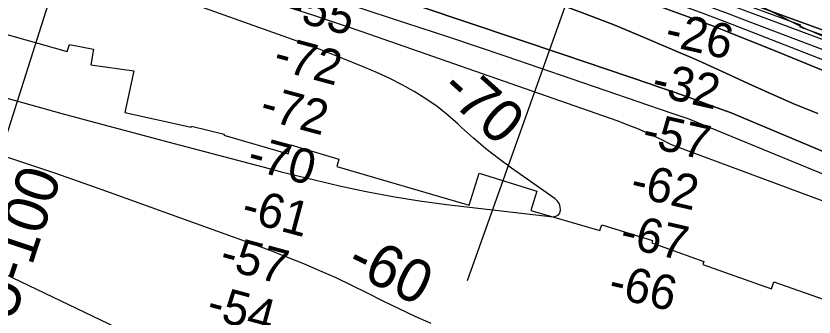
# Model space of a CAD drawing. Extents: x 3329297 to 3367176, y 649250 to 674653.
# Drawn here: x 3334604 to 3336153, y 670592 to 671176 of the extents above; entities that cross this region are included whole.
import ezdxf

# ---------------------------------------------------------------- set-up
doc = ezdxf.new("R2010")
doc.units = 0
for name, color, linetype in [('V-RIVR-EDGE', 7, 'Continuous'), ('V-RIVR-RANG', 7, 'Continuous'), ('V-RIVR-RANG-IDEN', 7, 'Continuous'), ('V-RRAP-RVMT', 7, 'Continuous'), ('V-TOPO-DPTH', 7, 'Continuous'), ('V-TOPO-MAJR', 7, 'Continuous'), ('V-TOPO-MINR', 7, 'Continuous'), ('V-TOPO-MINR-IDEN', 7, 'Continuous'), ('V-TOPO-WATR', 7, 'Continuous')]:
    doc.layers.add(name, color=color, linetype=linetype)

msp = doc.modelspace()

# ---------------------------------------------------------------- linework, layer by layer
at = {"layer": 'V-RIVR-EDGE'}
msp.add_spline([(3339166.4, 669632.4), (3339148.5, 669636.4), (3339138.8, 669636.8), (3339122.9, 669641.5), (3339105.1, 669646.9), (3339097, 669652), (3339093.1, 669656.3), (3339089.3, 669664.4), (3339086.6, 669669.1), (3339078.8, 669674.9), (3339053.6, 669688.2), (3339028.5, 669702.2), (3339020.7, 669706.5), (3339018, 669704.2), (3339012.6, 669704.6), (3339008.7, 669708.1), (3339008.3, 669710.4), (3339007.9, 669713.1), (3339007.6, 669715.1), (3338988.6, 669723.6), (3338974.6, 669732.6), (3338973.1, 669734.5), (3338972.7, 669738), (3338974.3, 669740.3), (3338974.3, 669743.8), (3338966.9, 669753.9), (3338965, 669758.6), (3338963.8, 669760.5), (3338956.5, 669764.4), (3338944.9, 669769.5), (3338928.2, 669778.1), (3338920.9, 669785.1), (3338906.6, 669803.3), (3338897.3, 669814.2), (3338888, 669824.7), (3338880.3, 669833.3), (3338874.1, 669838.7), (3338867.9, 669840.3), (3338862.1, 669843), (3338858.6, 669843), (3338858.6, 669845), (3338858.2, 669867.8), (3338860.6, 669870.9), (3338861.7, 669873.3), (3338861.8, 669876.4), (3338860.2, 669879.5), (3338854, 669882.6), (3338849, 669903.1), (3338843.6, 669917.5), (3338832.8, 669931.1), (3338822.7, 669940.8), (3338804.6, 669955.2), (3338800.7, 669956.8), (3338796, 669956.8), (3338788.7, 669955.3), (3338782.4, 669952.2), (3338775.5, 669955.7), (3338770.4, 669960.3), (3338765.4, 669965), (3338754.2, 669972.4), (3338742.6, 669981.4), (3338728.2, 669988.8), (3338714.7, 669995), (3338701.1, 670003.6), (3338693.4, 670012.1), (3338688, 670020.3), (3338682.6, 670033.5), (3338677.2, 670040.5), (3338665.2, 670046.3), (3338655.1, 670048.7), (3338655.5, 670045.9), (3338653.5, 670045.6), (3338643.5, 670046.4), (3338635.3, 670050.3), (3338633, 670053), (3338626.4, 670055.3), (3338615.2, 670057.3), (3338609, 670058.1), (3338601.6, 670062.8), (3338592.3, 670069.4), (3338582.2, 670071.7), (3338574.1, 670074.5), (3338568.3, 670078.7), (3338562.5, 670084.6), (3338561.3, 670087.7), (3338554.8, 670088.9), (3338551.3, 670089.3), (3338548.9, 670092), (3338544.3, 670098.6), (3338517.2, 670108.7), (3338513.3, 670111.8), (3338511.4, 670115.7), (3338497.8, 670118.9), (3338480, 670125.9), (3338471.5, 670130.2), (3338466.4, 670134.8), (3338451.7, 670140.3), (3338441.3, 670142.7), (3338438.2, 670142.3), (3338431.2, 670145.4), (3338420.3, 670150.1), (3338407.9, 670152.4), (3338393.2, 670156.7), (3338378.5, 670165.7), (3338345.2, 670189.4), (3338316.5, 670206.6), (3338280.9, 670231.5), (3338237.6, 670254.5), (3338210.4, 670270.8), (3338182.6, 670289.9), (3338148.9, 670317.5), (3338126.1, 670336.9), (3338116, 670348.2), (3338106.7, 670356.8), (3338093.6, 670363.8), (3338076.9, 670368.9), (3338057.5, 670376.3), (3338042.8, 670383.3), (3338026.5, 670392.6), (3338007.2, 670402.4), (3337994, 670405.5), (3337971.5, 670413.3), (3337948.7, 670420.8), (3337916.5, 670434), (3337912.6, 670440.6), (3337911.1, 670448.8), (3337908.8, 670453.8), (3337904.5, 670455.8), (3337891, 670459.7), (3337883.6, 670464.7), (3337879.4, 670466.7), (3337872.4, 670467.1), (3337862.7, 670467.1), (3337849.9, 670466), (3337839.8, 670463.7), (3337826.2, 670462.6), (3337810.7, 670465.7), (3337802.2, 670469.2), (3337788.3, 670478.2), (3337779.7, 670480.5), (3337774.3, 670481.7), (3337768.9, 670486.7), (3337764.6, 670490.6), (3337755.7, 670494.9), (3337749.1, 670496.9), (3337745.3, 670497.3), (3337740.6, 670495.3), (3337738.7, 670496.1), (3337735.2, 670499.2), (3337729.8, 670503.5), (3337724.7, 670508.2), (3337720.1, 670512.1), (3337706.1, 670514.4), (3337677.9, 670531.2), (3337643.8, 670545.2), (3337600.8, 670567), (3337560.1, 670585.4), (3337510.1, 670611.9), (3337463.3, 670636.4), (3337442.4, 670644.2), (3337416.8, 670652.4), (3337405.5, 670657.5), (3337401.7, 670661.4), (3337400.1, 670663.3), (3337395.5, 670665.7), (3337388.9, 670666.1), (3337376.9, 670670.8), (3337362.9, 670677.8), (3337340.9, 670690.6), (3337309.5, 670707), (3337291.3, 670714.8), (3337276.2, 670723), (3337252.6, 670737), (3337220, 670756.8), (3337155, 670798.5), (3337124.4, 670821.1), (3337111.2, 670827.3), (3337094.2, 670832.8), (3337076, 670836.7), (3337050.4, 670842.6), (3337028.7, 670849.6), (3337007.8, 670860.5), (3336991.9, 670867.9), (3336983.4, 670871.1), (3336969, 670873.4), (3336939.9, 670875.4), (3336902, 670884.4), (3336863.6, 670895.8), (3336821.4, 670910.6), (3336786.5, 670926.2), (3336740, 670949.6), (3336682.3, 670976.1), (3336635.4, 670997.2), (3336603.7, 671013.5), (3336585.5, 671022.5), (3336583.2, 671026.4), (3336580.1, 671031.1), (3336576.2, 671034.6), (3336549.5, 671045.1), (3336500.2, 671058), (3336451.4, 671070.2), (3336425.4, 671074.5), (3336399.8, 671076.5), (3336361.1, 671078.9), (3336337.4, 671082.8), (3336313.4, 671088.3), (3336290.9, 671094.6), (3336280.5, 671097.3), (3336275.4, 671097.3), (3336257.6, 671097.4), (3336194.8, 671123.9), (3336129.4, 671154.3), (3336078.6, 671179.7), (3336032.9, 671203), (3335979.5, 671230.3), (3335943, 671245.5), (3335907.8, 671259.2), (3335894.2, 671264.7), (3335887.6, 671265.5), (3335873.3, 671273.6), (3335871.4, 671277.1), (3335862.9, 671281.4), (3335831.1, 671293.5), (3335799.3, 671308.7), (3335763.7, 671327.4), (3335724.6, 671346.9), (3335714.5, 671352), (3335703.3, 671355.1), (3335699, 671358.2), (3335680, 671369.9), (3335645.9, 671385.5), (3335603.7, 671399.2), (3335573.1, 671406.6), (3335518.1, 671419.9), (3335470.4, 671436.7), (3335434, 671449.6), (3335405.3, 671466), (3335398, 671471), (3335385.9, 671471.1), (3335366.9, 671468.8), (3335346, 671463), (3335338.6, 671464.6), (3335338.6, 671467.3), (3335339, 671475.8), (3335337.9, 671478.9), (3335334.4, 671482), (3335319.7, 671486.7), (3335303, 671491), (3335280.1, 671488.4), (3335259.2, 671479.5), (3335245.6, 671472.2), (3335233.1, 671471.4), (3335223.8, 671474.2), (3335210.7, 671482), (3335198.7, 671485.9), (3335156.4, 671487.5), (3335124.6, 671488.4), (3335114.1, 671484.9), (3335094.7, 671474.1), (3335085.4, 671473.4), (3335075.3, 671475.7), (3335065.6, 671477.7), (3335064.9, 671478.5), (3335067.6, 671483.1), (3335066.8, 671484.7), (3335063.7, 671489.3), (3335039.7, 671501.4), (3335020.7, 671509.2), (3335003.3, 671512), (3334994.8, 671515.5), (3334990.9, 671517), (3334963, 671533.4), (3334933.2, 671549.4), (3334916.1, 671551.3), (3334894.4, 671557.6), (3334863.4, 671571.2), (3334847.9, 671581.8), (3334834.8, 671588), (3334809.2, 671598.5), (3334767.8, 671617.2), (3334744.9, 671627.8), (3334711.2, 671642.2), (3334691.4, 671649.2), (3334670.1, 671653.2), (3334647.6, 671659.8), (3334620.1, 671672.3), (3334605.4, 671678.5), (3334581, 671683.2), (3334555.8, 671689.1), (3334542.2, 671688.4), (3334534.1, 671688.8), (3334531.4, 671696.6), (3334523.7, 671706.3), (3334505.8, 671714.8), (3334480.3, 671719.2), (3334460.5, 671721.9), (3334457, 671720.4), (3334455, 671716.9), (3334456.6, 671713.8), (3334463.2, 671714.6), (3334467.4, 671712.2), (3334467.4, 671710.3), (3334462.8, 671708.4), (3334446.9, 671706.8), (3334429, 671707.7), (3334403.5, 671713.9), (3334397.7, 671718.6), (3334391.5, 671722.9), (3334378.7, 671723.7), (3334340.3, 671727.3), (3334305.4, 671730.1), (3334290.3, 671730.1), (3334281.3, 671731.7), (3334271.7, 671734.8), (3334266.2, 671735.6), (3334258.1, 671732.9), (3334246.4, 671726.7), (3334241.4, 671726.4), (3334232.5, 671729.5), (3334218.9, 671729.9), (3334190.6, 671730.7), (3334179, 671731.9), (3334163.5, 671737.4), (3334156.1, 671736.6), (3334151.4, 671732.4), (3334148.3, 671732.4), (3334142.5, 671735.9), (3334132.8, 671736.3), (3334110.7, 671737.5), (3334106.9, 671739.5), (3334099.9, 671744.2), (3334081.3, 671748.1), (3334072.8, 671747.7), (3334041.7, 671753.6), (3334018.1, 671757.5), (3334010.3, 671760.3), (3333999.9, 671767.7), (3333992.1, 671772), (3333987.1, 671771.2), (3333984.4, 671768.5), (3333980.1, 671768.5), (3333976.6, 671772.8), (3333969.7, 671775.1), (3333958.8, 671778.2), (3333949.9, 671783.3), (3333945.6, 671782.9), (3333941.4, 671782.2), (3333931.3, 671788), (3333925.9, 671788), (3333915.4, 671788.8), (3333900.3, 671791.6), (3333878.2, 671798.6), (3333856.9, 671811.1), (3333845.7, 671822.7), (3333832.9, 671829), (3333818.2, 671834.8), (3333817.4, 671837.2), (3333813.5, 671837.5), (3333800.4, 671841.8), (3333795.7, 671845), (3333793.8, 671851.6), (3333792.2, 671854.3), (3333782.9, 671858.2), (3333767.9, 671869.5), (3333755.5, 671879.6), (3333746.2, 671884.6), (3333742.7, 671886.2), (3333733.8, 671885.8), (3333721, 671886.6), (3333714.4, 671889.8), (3333707.8, 671895.2), (3333701.6, 671902.6), (3333697, 671908.4), (3333690.4, 671913.1), (3333677.2, 671920.5), (3333664.5, 671934.9), (3333650.9, 671945.8), (3333635, 671952), (3333625.8, 671959.8), (3333617.6, 671968.7), (3333606.4, 671969.9), (3333601, 671974.2), (3333597.9, 671978.1), (3333590.1, 671989), (3333572.4, 672009.2), (3333553.4, 672029.4), (3333532.1, 672045.7), (3333511.2, 672062.1), (3333486.4, 672080.3), (3333466.3, 672090.9), (3333451.6, 672102.9), (3333445.8, 672109.5), (3333446.6, 672115), (3333429.2, 672126.2), (3333421.4, 672137.9), (3333420.7, 672148.8), (3333415.3, 672151.1), (3333404.7, 672151.6)], degree=3, dxfattribs=at)
at = {"layer": 'V-RIVR-RANG'}
for p, q in [((3335003.7, 672263), (3334580, 670928.6)), ((3335950.1, 671980.4), (3335479.2, 670662))]:
    msp.add_line(p, q, dxfattribs=at)
at = {"layer": 'V-RRAP-RVMT'}
for p, q in [((3336127, 671158.3), (3336006.7, 671202)), ((3336125.6, 671154.2), (3336127, 671158.3)), ((3334566.8, 671145.2), (3334703.4, 671106.7)), ((3336227.2, 671118), (3336125.6, 671154.2)), ((3334703.4, 671106.7), (3334707.9, 671120.8)), ((3334707.9, 671120.8), (3334754.4, 671111.2)), ((3334754.4, 671111.2), (3334749, 671081.2)), ((3334749, 671081.2), (3334832.5, 671069.4)), ((3334832.5, 671069.4), (3334814.9, 670988.7)), ((3334814.9, 670988.7), (3334944, 670960.2)), ((3334944, 670960.2), (3334944.5, 670962.2)), ((3334944.5, 670962.2), (3335007.6, 670946.7)), ((3335007.6, 670946.7), (3335007.1, 670944.4)), ((3335007.1, 670944.4), (3335131.8, 670908.6)), ((3335131.8, 670908.6), (3335137.1, 670925.7)), ((3335137.1, 670925.7), (3335230.3, 670898.2)), ((3335230.3, 670898.2), (3335226.6, 670884)), ((3335226.6, 670884), (3335483.5, 670808.9)), ((3335483.5, 670808.9), (3335502.6, 670870.7)), ((3335502.6, 670870.7), (3335614.9, 670836.4)), ((3335614.9, 670836.4), (3335602.7, 670798.5)), ((3335602.7, 670798.5), (3335736.8, 670760.1)), ((3335736.8, 670760.1), (3335740.6, 670771.1)), ((3335740.6, 670771.1), (3335839, 670740.3)), ((3335839, 670740.3), (3335837.7, 670735.8)), ((3335837.7, 670735.8), (3335938.8, 670699.4)), ((3335938.8, 670699.4), (3335936.7, 670693.7)), ((3335936.7, 670693.7), (3336069.9, 670646.6)), ((3336069.9, 670646.6), (3336074.6, 670660.3)), ((3336074.6, 670660.3), (3336183.3, 670622.4))]:
    msp.add_line(p, q, dxfattribs=at)
at = {"layer": 'V-TOPO-DPTH'}
for points in [[(3334414.8, 671708.4), (3335247.6, 671481.7), (3335255, 671479.7), (3335262.3, 671477.6), (3335269.6, 671475.4), (3335276.9, 671473.1), (3335284.2, 671470.8), (3335291.5, 671468.4), (3335298.7, 671465.9), (3335305.9, 671463.3), (3335880.5, 671254.6), (3335895, 671249.3), (3335909.5, 671244), (3335924, 671238.7), (3335938.5, 671233.3), (3335958.7, 671225.9), (3335963.1, 671224.3), (3335967.5, 671222.6), (3335972, 671221), (3335976.4, 671219.4), (3336088.2, 671178.3), (3336148.6, 671156.1), (3336208.9, 671133.8)], [(3336208.9, 671133.8), (3336148.6, 671156.1), (3336088.2, 671178.3), (3335976.4, 671219.4), (3335972, 671221), (3335967.5, 671222.6), (3335963.1, 671224.3), (3335958.7, 671225.9), (3335938.5, 671233.3), (3335924, 671238.7), (3335909.5, 671244), (3335895, 671249.3), (3335880.5, 671254.6), (3335305.9, 671463.3), (3335298.7, 671465.9), (3335291.5, 671468.4), (3335284.2, 671470.8), (3335276.9, 671473.1), (3335269.6, 671475.4), (3335262.3, 671477.6), (3335255, 671479.7), (3335247.6, 671481.7), (3334414.8, 671708.4)], [(3336568.3, 670959.4), (3336013.3, 671169.7), (3335986.6, 671179.7), (3335959.9, 671189.7), (3335933.2, 671199.6), (3335906.5, 671209.5), (3335826.2, 671239), (3335759.3, 671263.3), (3335692.1, 671287.1), (3335624.8, 671310.4), (3335557.4, 671333.3), (3335330, 671409.2), (3335304.9, 671417.4), (3335279.7, 671425.4), (3335254.4, 671433), (3335229, 671440.4), (3334753, 671576.1), (3334687.6, 671594.6), (3334622.2, 671613.1), (3334556.7, 671631.3)], [(3336568.3, 670959.4), (3336013.3, 671169.7), (3335986.6, 671179.7), (3335959.9, 671189.7), (3335933.2, 671199.6), (3335906.5, 671209.5), (3335826.2, 671239), (3335759.3, 671263.3), (3335692.1, 671287.1), (3335624.8, 671310.4), (3335557.4, 671333.3), (3335330, 671409.2), (3335304.9, 671417.4), (3335279.7, 671425.4), (3335254.4, 671433), (3335229, 671440.4), (3334753, 671576.1), (3334687.6, 671594.6), (3334622.2, 671613.1), (3334556.7, 671631.3)], [(3334388.2, 671617), (3334613, 671565.5), (3334723.3, 671539.6), (3334833.5, 671513), (3334943.4, 671485.3), (3335053.2, 671456.8), (3335248.6, 671404.9), (3335260.4, 671401.7), (3335272.3, 671398.3), (3335284, 671394.7), (3335295.7, 671391), (3335373.3, 671365.6), (3335423.7, 671348.8), (3335473.9, 671331.7), (3335524, 671314.1), (3335574, 671296.1), (3335929.9, 671166.1), (3335941.2, 671161.9), (3335952.5, 671157.7), (3335963.8, 671153.3), (3335975, 671148.9), (3336067.1, 671112.2), (3336124.2, 671089), (3336181.1, 671065.3)], [(3336181.1, 671065.3), (3336124.2, 671089), (3336067.1, 671112.2), (3335975, 671148.9), (3335963.8, 671153.3), (3335952.5, 671157.7), (3335941.2, 671161.9), (3335929.9, 671166.1), (3335574, 671296.1), (3335524, 671314.1), (3335473.9, 671331.7), (3335423.7, 671348.8), (3335373.3, 671365.6), (3335295.7, 671391), (3335284, 671394.7), (3335272.3, 671398.3), (3335260.4, 671401.7), (3335248.6, 671404.9), (3335053.2, 671456.8), (3334943.4, 671485.3), (3334833.5, 671513), (3334723.3, 671539.6), (3334613, 671565.5), (3334388.2, 671617)], [(3334519.3, 671499.2), (3334616.5, 671474.7), (3334713.8, 671450.9), (3334811.4, 671428.4), (3334909.3, 671406.5), (3335200.3, 671343.3), (3335227.2, 671337.1), (3335253.9, 671330.3), (3335280.3, 671322.7), (3335306.7, 671314.5), (3335592.6, 671221), (3335650.8, 671201.1), (3335708.7, 671180.2), (3335765.9, 671157.8), (3335822.8, 671134.3), (3335889.7, 671105.7), (3335912.8, 671095.7), (3335935.8, 671085.6), (3335958.7, 671075.2), (3335981.6, 671064.8), (3336024.9, 671044.8), (3336069.5, 671024.7), (3336114.4, 671005.1), (3336159.7, 670986.5)], [(3334519.3, 671499.2), (3334616.5, 671474.7), (3334713.8, 671450.9), (3334811.4, 671428.4), (3334909.3, 671406.5), (3335200.3, 671343.3), (3335227.2, 671337.1), (3335253.9, 671330.3), (3335280.3, 671322.7), (3335306.7, 671314.5), (3335592.6, 671221), (3335650.8, 671201.1), (3335708.7, 671180.2), (3335765.9, 671157.8), (3335822.8, 671134.3), (3335889.7, 671105.7), (3335912.8, 671095.7), (3335935.8, 671085.6), (3335958.7, 671075.2), (3335981.6, 671064.8), (3336024.9, 671044.8), (3336069.5, 671024.7), (3336114.4, 671005.1), (3336159.7, 670986.5)], [(3336780.8, 670656.1), (3335991.8, 670987.8), (3335955.6, 671001.1), (3335919.3, 671014.3), (3335882.8, 671027.2), (3335846.3, 671039.8), (3335835.6, 671043.5), (3335793.7, 671057.8), (3335751.7, 671072.1), (3335709.8, 671086.3), (3335667.8, 671100.5), (3335296, 671225.8), (3335263.7, 671236.5), (3335231.4, 671247), (3335199, 671257.2), (3335166.5, 671267.3), (3335055.9, 671301), (3334968, 671327.5), (3334879.9, 671353.6), (3334791.7, 671379.1), (3334703.4, 671404.2), (3334375.4, 671496.3)], [(3334375.4, 671496.3), (3334703.4, 671404.2), (3334791.7, 671379.1), (3334879.9, 671353.6), (3334968, 671327.5), (3335055.9, 671301), (3335166.5, 671267.3), (3335199, 671257.2), (3335231.4, 671247), (3335263.7, 671236.5), (3335296, 671225.8), (3335667.8, 671100.5), (3335709.8, 671086.3), (3335751.7, 671072.1), (3335793.7, 671057.8), (3335835.6, 671043.5), (3335846.3, 671039.8), (3335882.8, 671027.2), (3335919.3, 671014.3), (3335955.6, 671001.1), (3335991.8, 670987.8), (3336780.8, 670656.1)]]:
    msp.add_lwpolyline(points, dxfattribs=at)
at = {"layer": 'V-TOPO-MAJR'}
for points in [[(3336703.6, 670649.6), (3335910.2, 670975.4), (3335892.7, 670981.5), (3335875.2, 670987.6), (3335554.9, 671097), (3335499.4, 671115.8), (3335443.7, 671134.5), (3335388, 671152.9), (3335332.3, 671171.1), (3335245.6, 671199.1), (3335233.1, 671203.1), (3335220.6, 671207.1), (3335208, 671210.9), (3335195.4, 671214.7), (3334355.2, 671464.4)], [(3334192.5, 670861.7), (3335001.2, 670474.8)]]:
    msp.add_lwpolyline(points, dxfattribs=at)
at = {"layer": 'V-TOPO-MINR'}
for points in [[(3336645.9, 670952.8), (3336032.9, 671180.5), (3335998.3, 671193.3), (3335963.7, 671206.1), (3335929.1, 671218.9), (3335894.6, 671231.7), (3335882.5, 671236.1), (3335841.8, 671251), (3335801, 671265.6), (3335760.2, 671280), (3335719.3, 671294.3), (3335352.7, 671420.8), (3335318.7, 671432.2), (3335284.6, 671443.4), (3335250.4, 671454.2), (3335216, 671464.6), (3335115.5, 671494.5), (3335030.7, 671519.3), (3334945.8, 671543.8), (3334860.8, 671567.8), (3334775.7, 671591.3), (3334427.5, 671686.5)], [(3336568.3, 670959.4), (3336013.3, 671169.7), (3335986.6, 671179.7), (3335959.9, 671189.7), (3335933.2, 671199.6), (3335906.5, 671209.5), (3335826.2, 671239), (3335759.3, 671263.3), (3335692.1, 671287.1), (3335624.8, 671310.4), (3335557.4, 671333.3), (3335330, 671409.2), (3335304.9, 671417.4), (3335279.7, 671425.4), (3335254.4, 671433), (3335229, 671440.4), (3334753, 671576.1), (3334687.6, 671594.6), (3334622.2, 671613.1), (3334556.7, 671631.3)], [(3336181.1, 671065.3), (3336124.2, 671089), (3336067.1, 671112.2), (3335975, 671148.9), (3335963.8, 671153.3), (3335952.5, 671157.7), (3335941.2, 671161.9), (3335929.9, 671166.1), (3335574, 671296.1), (3335524, 671314.1), (3335473.9, 671331.7), (3335423.7, 671348.8), (3335373.3, 671365.6), (3335295.7, 671391), (3335284, 671394.7), (3335272.3, 671398.3), (3335260.4, 671401.7), (3335248.6, 671404.9), (3335053.2, 671456.8), (3334943.4, 671485.3), (3334833.5, 671513), (3334723.3, 671539.6), (3334613, 671565.5), (3334388.2, 671617)], [(3336275.8, 671049.7), (3335993.9, 671159.1), (3335975.1, 671166.4), (3335956.2, 671173.6), (3335937.2, 671180.6), (3335918.3, 671187.6), (3335735.6, 671254.6), (3335659.4, 671282.1), (3335583.1, 671309), (3335506.4, 671335.1), (3335429.6, 671360.7), (3335311.4, 671399.5), (3335293.6, 671405.2), (3335275.6, 671410.7), (3335257.6, 671416), (3335239.6, 671421.1), (3334519.3, 671619.5)], [(3336159.7, 670986.5), (3336114.4, 671005.1), (3336069.5, 671024.7), (3336024.9, 671044.8), (3335981.6, 671064.8), (3335958.7, 671075.2), (3335935.8, 671085.6), (3335912.8, 671095.7), (3335889.7, 671105.7), (3335822.8, 671134.3), (3335765.9, 671157.8), (3335708.7, 671180.2), (3335650.8, 671201.1), (3335592.6, 671221), (3335306.7, 671314.5), (3335280.3, 671322.7), (3335253.9, 671330.3), (3335227.2, 671337.1), (3335200.3, 671343.3), (3334909.3, 671406.5), (3334811.4, 671428.4), (3334713.8, 671450.9), (3334616.5, 671474.7), (3334519.3, 671499.2)], [(3336780.8, 670656.1), (3335991.8, 670987.8), (3335955.6, 671001.1), (3335919.3, 671014.3), (3335882.8, 671027.2), (3335846.3, 671039.8), (3335835.6, 671043.5), (3335793.7, 671057.8), (3335751.7, 671072.1), (3335709.8, 671086.3), (3335667.8, 671100.5), (3335296, 671225.8), (3335263.7, 671236.5), (3335231.4, 671247), (3335199, 671257.2), (3335166.5, 671267.3), (3335055.9, 671301), (3334968, 671327.5), (3334879.9, 671353.6), (3334791.7, 671379.1), (3334703.4, 671404.2), (3334375.4, 671496.3)], [(3334358.3, 671422.8), (3335013.2, 671229.8), (3335046.1, 671219.9), (3335079, 671209.9), (3335111.8, 671199.7), (3335144.6, 671189.3), (3335177.3, 671178.6), (3335209.9, 671167.8), (3335242.4, 671156.8), (3335274.9, 671145.6), (3335769.8, 670972.8), (3335791.5, 670964.8), (3335813, 670956.2), (3335834.1, 670946.8), (3335855, 670936.9), (3335875, 670926.9), (3336707.5, 670617.4)], [(3334584, 671017.1), (3334692.8, 670987), (3334801.8, 670957.5), (3334910.9, 670928.4), (3335107.8, 670876.5), (3335118.6, 670873.7), (3335129.4, 670871), (3335140.2, 670868.3), (3335151, 670865.7), (3335231.9, 670846.6), (3335283.4, 670835.5), (3335335.1, 670825.5), (3335387, 670817.3), (3335439.2, 670810.4), (3335646, 670786.6), (3335651.6, 670787.4), (3335656.1, 670789.6), (3335659, 670793.7), (3335660.8, 670799.1), (3335660.1, 670805.6), (3335658.3, 670811.6), (3335654.7, 670816.8), (3335649.9, 670821.4), (3335565.7, 670880.6), (3335540.4, 670899.2), (3335515.8, 670918.4), (3335492, 670938.7), (3335468.7, 670959.6), (3335462, 670965.9), (3335442, 670983.5), (3335421.2, 671000.1), (3335399.3, 671015.2), (3335376.7, 671029.4), (3335353.3, 671042.3), (3335329.5, 671054.5), (3335305.2, 671065.6), (3335280.7, 671076.1), (3335218.8, 671100.9), (3335206.6, 671105.7), (3335194.3, 671110.5), (3335182, 671115.1), (3335169.7, 671119.6), (3334875, 671225.2)], [(3334583.4, 670903.6), (3334680.8, 670870.9), (3334777.8, 670837), (3335064.8, 670733.5), (3335077.1, 670729), (3335089.4, 670724.4), (3335101.5, 670719.7), (3335113.7, 670714.8), (3335161.6, 670695.6), (3335193.1, 670682.4), (3335224.3, 670668.7), (3335255.1, 670654), (3335285.6, 670638.7), (3335316.1, 670623.3), (3335346.8, 670608.3), (3335377.8, 670593.9), (3335409, 670580)]]:
    msp.add_lwpolyline(points, dxfattribs=at)
at = {"layer": 'V-TOPO-WATR'}
msp.add_lwpolyline([(3336208.9, 671133.8), (3336148.6, 671156.1), (3336088.2, 671178.3), (3335976.4, 671219.4), (3335972, 671221), (3335967.5, 671222.6), (3335963.1, 671224.3), (3335958.7, 671225.9), (3335938.5, 671233.3), (3335924, 671238.7), (3335909.5, 671244), (3335895, 671249.3), (3335880.5, 671254.6), (3335305.9, 671463.3), (3335298.7, 671465.9), (3335291.5, 671468.4), (3335284.2, 671470.8), (3335276.9, 671473.1), (3335269.6, 671475.4), (3335262.3, 671477.6), (3335255, 671479.7), (3335247.6, 671481.7), (3334414.8, 671708.4)], dxfattribs=at)

# ---------------------------------------------------------------- texts
at = {"layer": 'V-RIVR-RANG'}
for s, rotation, p in [('-55', 344.9591, (3335125.8, 671170.8)), ('-26', 347.1278, (3335860.2, 671119.9)), ('-72', 344.9591, (3335100.1, 671074.1)), ('-32', 347.1278, (3335834.6, 671023.1)), ('-72', 344.9591, (3335073.9, 670977.6)), ('-57', 347.1278, (3335815.9, 670924.8)), ('-70', 344.9591, (3335049.5, 670880.6)), ('-62', 347.1278, (3335793.2, 670827.4)), ('-61', 344.9591, (3335038.1, 670780.2)), ('-67', 347.1278, (3335773, 670729.5)), ('-57', 344.9591, (3334996.1, 670687.9)), ('-66', 347.1278, (3335750.7, 670632)), ('-54', 344.9591, (3334970.5, 670591.3))]:
    msp.add_text(s, height=67, rotation=rotation, dxfattribs=at).set_placement(p)
at = {"layer": 'V-RIVR-RANG-IDEN'}
msp.add_text('U-100', height=83, rotation=71.6589, dxfattribs=at).set_placement((3334597.8, 670578.7))
at = {"layer": 'V-TOPO-MINR-IDEN'}
for s, rotation, p in [('-70', 317.9929, (3335423.3, 671028.5)), ('-60', 333.9597, (3335241.2, 670683))]:
    msp.add_text(s, height=83, rotation=rotation, dxfattribs=at).set_placement(p)

doc.saveas('drawing.dxf')
